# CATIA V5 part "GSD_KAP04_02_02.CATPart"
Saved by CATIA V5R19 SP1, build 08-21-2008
Part number: GSD_KAP04_02_02
Definition: Beispielmodell für Kapitel 4 - Sketcher.
Description: CATIA V5 Flächenmodellierung  Copyright (c) 2009 Maik Hertha IT Consultants
Bounding box of the stored display mesh (mm): x -134.998 to 40, y 0 to 0, z -55 to 55
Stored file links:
  \GSD_BUCH_UEBUNG\GSD_KAP04_02_02.CATPart
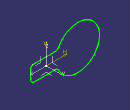
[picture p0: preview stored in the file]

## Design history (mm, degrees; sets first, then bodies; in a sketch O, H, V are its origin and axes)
AxisSystem1: origin (0, 0, 0), X (1, 0, 0), Y (0, 1, 0), Z (0, 0, 1)
Set1
  Sketch1 on zx-plane, origin (0, 0, 0), H (-1, 0, 0), V (0, 0, 1)
    point P1 (-35, 20)
    line L1 (-35, 20) -> (22.3372, 20)
    arc A1 centre (22.3372, 30) radius 10 from (22.3372, 20) to (31.2084, 25.3846) ccw
    arc A2 centre (80, 0) radius 55 from (31.2084, 25.3846) to (31.2084, -25.3846) cw
    point P5 (80, 0)
    arc A3 centre (22.3372, -30) radius 10 from (31.2084, -25.3846) to (22.3372, -20) ccw
    line L2 (22.3372, -20) -> (-30, -20)
    arc A4 centre (-30, -10) radius 10 from (-30, -20) to (-40, -10) cw
    line L3 (-40, -10) -> (-40, 15)
    line L4 (-40, 15) -> (-35, 20)
    radius A2 = 55
    radius A1 = 10
    radius A3 = 10
    radius A4 = 10
    distance P5 H = 0
    distance L1 L2 = 40
    distance P5 V = 80
    distance L3 V = 40
    distance L3 P1 = 5
    angle L4 L1 = 45
    tangency: A1 A2, A1 L1, A3 A2, A3 L2, A4 L2, A4 L3
    symmetry: L1 L2 H
    vertical: L3 V
Body1 (main body)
